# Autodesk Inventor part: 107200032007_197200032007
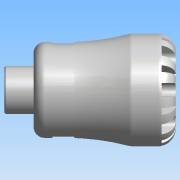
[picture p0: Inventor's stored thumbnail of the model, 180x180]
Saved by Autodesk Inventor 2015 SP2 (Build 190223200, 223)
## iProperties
Created: 2016-12
Part Number: 107200032007_197200032007
Material: PVC-Piping
Description: PLASSON MALE INTEGRAL BRASS THREAD 32X3/4" SERIES 1
Document SubType Name: Modeling
Designer: KIM
Mass: 61.7504 g
Surface Area: 140.097 cm^2
Volume: 44.1074 cm^3
Density: 1.4 g/cm^3
Appearance: Smooth - White
Author: KIM
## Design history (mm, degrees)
derived "1072.ipt"
feature "Solid1::1072.ipt"
tag "TaggingFeature1"
body "Solid1"
other parameters: "d0" = 88, "d1" = 23.1, "d2" = 32, "d4" = 58, "d6" = 55, "d8" = 49.3, "d13" = 7.2, "d14" = 7.2, "d15" = 0, "d17" = 360 deg, "d19" = 8 deg, "d20" = 0.64, "d21" = 0.64, "d22" = 8 deg, "d24" = 0, "d26" = 360 deg, "d32" = 5.8, "d33" = 5.8, "d34" = 24.658, "d38" = 15, "d39" = 0.73974, "d42" = 11.2, "d43" = 7.36, "d45" = 14.112, "d46" = 0, "d59" = 360 deg, "d61" = 9.52, "d62" = 0.64, "d64" = 0, "d65" = 0.58, "d68" = 4.57143, "d_" = 32, "E_" = 58, "H_" = 88, "l_" = 55, "R_" = 24.658, "l_2" = 15, "d9" = 9, "d11" = 58
